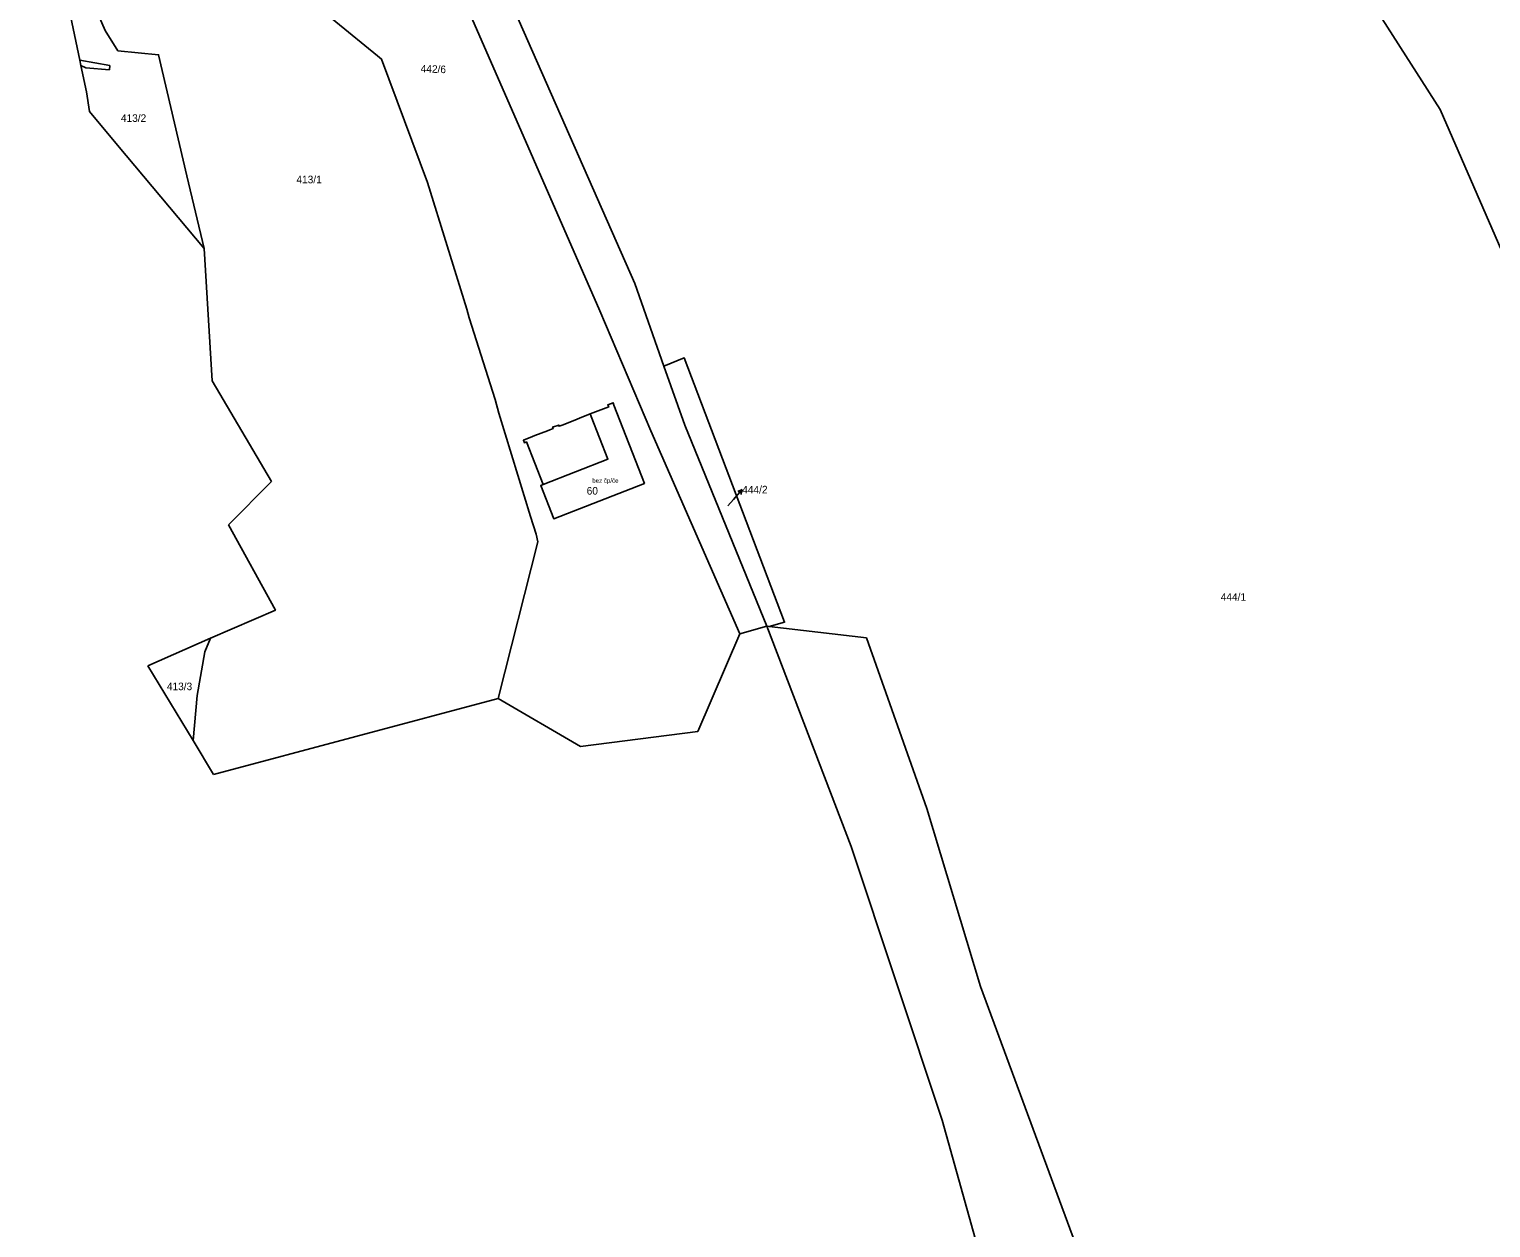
# Model space of a CAD drawing. Extents: x -880531 to -877616, y -1023932 to -1021350.
# Drawn here: x -880243.3 to -879914.9, y -1023200.5 to -1022931.1 of the extents above; entities that cross this region are included whole.
import ezdxf

# ---------------------------------------------------------------- set-up
doc = ezdxf.new("R2010")
doc.units = 0
for name, color, linetype in [('Definiční body', 7, 'Continuous'), ('Hranice parcel', 7, 'Continuous'), ('Parcelní čísla', 7, 'Continuous'), ('Polygon budovy', 7, 'Continuous'), ('Pop  PČ popisy', 7, 'Continuous'), ('Vnitřní kresba', 7, 'Continuous')]:
    doc.layers.add(name, color=color, linetype=linetype)

msp = doc.modelspace()

# ---------------------------------------------------------------- linework, layer by layer
at = {"layer": 'Hranice parcel'}
for p, q in [((-880231.98, -1022938.01), (-880235.4, -1022921.54)), ((-880204.04, -1022980.32), (-880223.5, -1022957.1)), ((-880198.56, -1023042.48), (-880188.9, -1023032.74)), ((-880138, -1023081.51), (-880129.04, -1023046.29)), ((-880216.7, -1023074.16), (-880202.65, -1023067.93)), ((-880093.11, -1023088.89), (-880083.68, -1023066.92)), ((-880083.68, -1023066.92), (-880077.59, -1023065.26)), ((-880077.59, -1023065.26), (-880077.12, -1023065.31)), ((-880206.52, -1023090.97), (-880216.7, -1023074.16)), ((-880201.92, -1023098.58), (-880138, -1023081.51)), ((-880206.52, -1023090.97), (-880201.92, -1023098.58))]:
    msp.add_line(p, q, dxfattribs=at)
for points in [[(-880189.68, -1022867.94), (-880186.63, -1022866.58), (-880188.91, -1022861.28), (-880180.55, -1022856.51), (-880188.62, -1022834.25), (-880191.78, -1022835.57), (-880191.23, -1022832.04), (-880189.34, -1022824.54), (-880188.21, -1022820.18), (-880182.52, -1022840.37), (-880174.52, -1022862.04), (-880144.98, -1022926.17), (-880115.13, -1022994.32), (-880103.69, -1023021.35), (-880083.68, -1023066.92)], [(-879967.14, -1022885.22), (-879926.31, -1022949.08), (-879906.41, -1022994.89), (-879898.19, -1023014.67), (-879871.37, -1023071.65), (-879843.32, -1023124.08), (-879802.44, -1023195.78)], [(-880243.35, -1022890.07), (-880241.64, -1022893.66), (-880238.09, -1022904.18), (-880237.6, -1022905.22), (-880226.25, -1022931.35), (-880223.43, -1022935.9), (-880214.29, -1022936.81), (-880207.9, -1022964), (-880204.04, -1022980.32)], [(-880129.04, -1023046.29), (-880129.43, -1023044.54), (-880130.69, -1023040.62), (-880137.84, -1023017.32), (-880138.66, -1023014.32), (-880144.53, -1022995.91), (-880145.04, -1022993.98), (-880153.89, -1022965.48), (-880164.21, -1022937.78), (-880165.13, -1022937.04), (-880174.46, -1022929.37), (-880190.85, -1022916.02), (-880200.32, -1022903.66)], [(-880100.73, -1023006.79), (-880107.25, -1022988.21), (-880135.5, -1022924.1)], [(-880223.5, -1022957.1), (-880229.78, -1022949.56), (-880230.5, -1022945.1), (-880231.72, -1022939.23), (-880231.98, -1022938.01)], [(-880188.9, -1023032.74), (-880202.24, -1023010.12), (-880204.04, -1022980.32)], [(-880100.73, -1023006.79), (-880096.17, -1023004.93), (-880073.63, -1023064.34), (-880077.12, -1023065.31)], [(-880077.59, -1023065.26), (-880096.07, -1023020.09), (-880100.73, -1023006.79)], [(-880113.14, -1023015.95), (-880117.31, -1023017.53), (-880119.68, -1023018.48), (-880120.22, -1023018.71), (-880123.03, -1023019.81), (-880123.57, -1023020.04), (-880124.29, -1023020.31), (-880124.38, -1023020.05), (-880125.77, -1023020.5), (-880125.65, -1023020.83), (-880126.37, -1023021.1), (-880126.93, -1023021.35), (-880129.73, -1023022.37), (-880130.28, -1023022.62), (-880132.31, -1023023.43), (-880132.09, -1023023.99), (-880131.63, -1023023.8), (-880127.85, -1023033.36), (-880128.4, -1023033.58), (-880125.5, -1023041.09), (-880105.12, -1023033.15), (-880111.96, -1023015.59), (-880112.13, -1023015.01), (-880113.34, -1023015.51), (-880113.14, -1023015.95)], [(-880202.65, -1023067.93), (-880188.04, -1023061.62), (-880198.56, -1023042.48)], [(-880202.65, -1023067.93), (-880203.87, -1023070.99), (-880205.58, -1023080.83), (-880206.52, -1023090.97)], [(-880009.23, -1023276.92), (-880020.51, -1023239.61), (-880038.19, -1023176.27), (-880058.64, -1023114.79), (-880077.59, -1023065.26)], [(-880077.12, -1023065.31), (-880055.22, -1023067.87), (-880041.66, -1023106.22), (-880029.62, -1023146.23), (-880004.11, -1023215.22), (-879985.57, -1023257.44), (-879802.44, -1023195.78)], [(-880093.11, -1023088.89), (-880119.5, -1023092.28), (-880138, -1023081.51)]]:
    msp.add_lwpolyline(points, dxfattribs=at)
at = {"layer": 'Polygon budovy'}
msp.add_lwpolyline([(-880127.85, -1023033.36), (-880128.4, -1023033.58), (-880125.5, -1023041.09), (-880105.12, -1023033.15), (-880111.96, -1023015.59), (-880112.13, -1023015.01), (-880113.34, -1023015.51), (-880113.14, -1023015.95), (-880117.31, -1023017.53), (-880117.05, -1023018.07), (-880113.33, -1023027.7)], close=True, dxfattribs=at)
at = {"layer": 'Pop  PČ popisy'}
for p, q in [((-880085.13, -1023036.78), (-880083.122, -1023034.55)), ((-880083.122, -1023034.55), (-880084.164, -1023034.959)), ((-880083.122, -1023034.55), (-880083.42, -1023035.629)), ((-880086.35, -1023038.15), (-880085.13, -1023036.78))]:
    msp.add_line(p, q, dxfattribs=at)
at = {"layer": 'Vnitřní kresba'}
for p, q in [((-880231.98, -1022938.01), (-880225.26, -1022939.18)), ((-880231.72, -1022939.23), (-880230.6, -1022939.75)), ((-880230.6, -1022939.75), (-880225.34, -1022940.18)), ((-880225.34, -1022940.18), (-880225.26, -1022939.18)), ((-880117.31, -1023017.53), (-880117.05, -1023018.07)), ((-880117.05, -1023018.07), (-880113.33, -1023027.7)), ((-880127.85, -1023033.36), (-880113.33, -1023027.7))]:
    msp.add_line(p, q, dxfattribs=at)

# ---------------------------------------------------------------- texts
at = {"layer": 'Definiční body'}
msp.add_text('bez čp/če', height=1, dxfattribs=at).set_placement((-880116.84, -1023033.01))
at = {"layer": 'Parcelní čísla'}
msp.add_text('442/6', height=1.7, rotation=358, dxfattribs=at).set_placement((-880155.419, -1022940.749))
for s, p in [('413/2', (-880222.75, -1022951.88)), ('413/1', (-880183.31, -1022965.68)), ('60', (-880118.09, -1023035.66)), ('444/2', (-880083.14, -1023035.39)), ('444/1', (-879975.62, -1023059.52)), ('413/3', (-880212.42, -1023079.62))]:
    msp.add_text(s, height=1.7, dxfattribs=at).set_placement(p)

doc.saveas('drawing.dxf')
